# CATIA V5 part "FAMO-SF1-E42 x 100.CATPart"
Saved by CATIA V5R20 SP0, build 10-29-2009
Part number: FAMO-SF1-E42 x 100
Definition: NONE
Nomenclature: FAMO-SF1-E42 x 100
Source: Unknown
Description: FAMO-SF1-E42 x 100
Bounding box of the stored display mesh (mm): x -70 to 30, y -31.5 to 31.5, z -31.5 to 31.5
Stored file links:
  C:\Users\Utente\Desktop\IO LAVORO\3D X SITO CF\X SITO\FAMO\FAMO-SF1-E42 x 100.CATPart
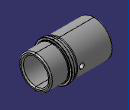
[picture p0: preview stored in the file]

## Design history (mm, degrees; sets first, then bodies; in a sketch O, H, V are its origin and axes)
Body1 "FAMO-SF1-E42 x 100" (main body)
  Solid1: solid without history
